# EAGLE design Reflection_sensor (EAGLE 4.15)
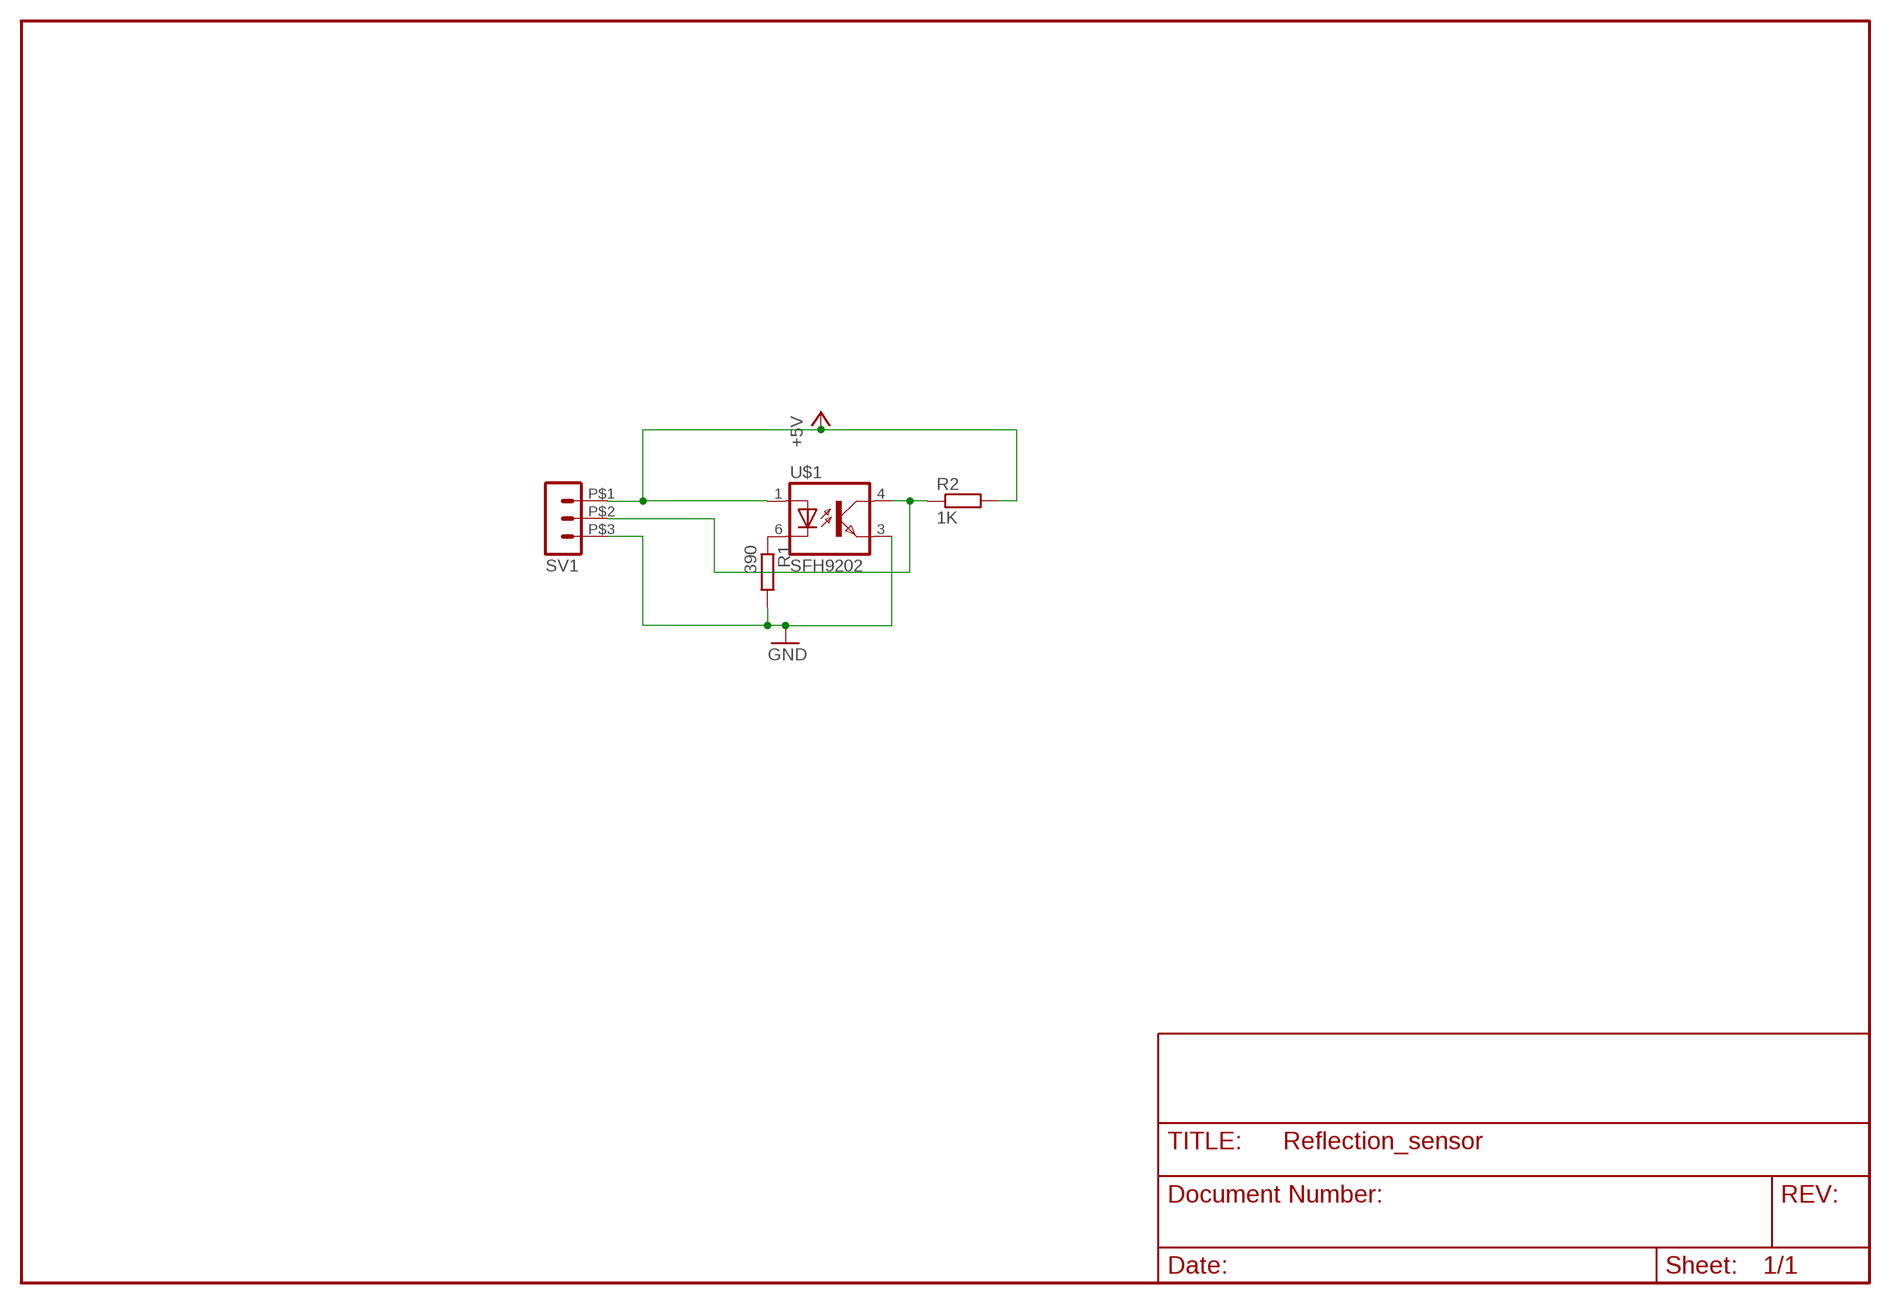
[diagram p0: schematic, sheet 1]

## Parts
R1  390  R-EU_M0805  [M0805]
R2  1K  R-EU_M0805  [M0805]
SV1  MA03-1HOLE  [MA03-1]
U$1  SFH9202  [SFH9202]

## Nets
+5V: R2.2 SV1.P$1 U$1.1(A)
GND: R1.2 SV1.P$3 U$1.3(EMIT)
N$1: R2.1 SV1.P$2 U$1.4(COL)
N$2: R1.1 U$1.6(C)

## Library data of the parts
R1 R2 = rcl:R-EU_: RESISTOR, European symbol
SV1 = Evert:MA03-1: PIN HEADER
U$1 = Evert:SFH9202

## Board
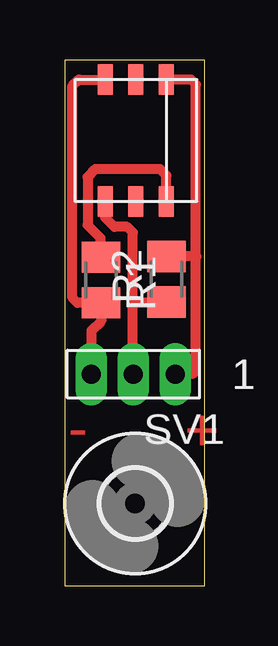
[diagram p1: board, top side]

Size 5.85 x 21.9 mm. Coordinates in mm from the lower left corner, seen from the top.
Outline: 0,0 5.85,0 5.85,21.9 0,21.9 0,0
Copper layers (1*16): Top 0.035mm / dielectric 1.5mm / Bottom 0.035mm
Design rules "default": minimum track width 10mil, minimum drill 24mil, track to track 8mil, track to pad 8mil, pad to pad 8mil, via to via 8mil, smd to smd 8mil, copper to edge 40mil, drill to drill 8mil, minimum pad ring 10mil, minimum via ring 8mil, stop-mask expansion 4mil, vias tented up to drill 0mil, thermal gap 10mil

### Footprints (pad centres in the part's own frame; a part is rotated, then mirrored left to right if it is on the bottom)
M0805 = smd 1.3 x 1.6: 1 -0.95,0; 2 0.95,0
MA03-1 = drill 0.8 long: P$1 -1.75,0; P$2 0,0; P$3 1.75,0
SFH9202 = smd 1.27 x 0.635: 1 -2.54,1.27; 2 -2.54,0; 3 -2.54,-1.27; 4 2.54,-1.27; 5 2.54,0; 6 2.54,1.27
2,8 = hole 2.8: 0,0

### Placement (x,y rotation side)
R1  1.52,12.73 270 top
R2  4.24,12.76 90 top
SV1  2.87,8.8 180 top
U$1  2.97,18.54 270 top
U$2  [2,8]  2.94,3.42 0 top

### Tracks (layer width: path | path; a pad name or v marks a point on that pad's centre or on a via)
+5V
  Top 0.406: U$1.1 5.28,21.08 5.47,20.89 5.47,13.72 | 5.47,13.72 5.47,8.94 5.36,8.83 4.61,8.83 4.62,8.82 SV1.P$1 | 5.47,13.72 5.5,13.72 5.5,13.71 R2.2
GND
  Top 0.406: U$1.3 0.6,21.08 0.33,20.82 0.33,11.99 0.54,11.78 1.47,11.78 1.49,11.76 R1.2 1.52,11.02 1.12,10.62 SV1.P$3
N$1
  Top 0.406: U$1.4 1.7,15.32 2.08,14.95 2.61,14.95 2.84,14.72 2.84,11.81 | SV1.P$2 2.89,8.83 2.84,8.87 2.84,11.81 | SV1.P$2 | 2.84,11.81 2.87,11.81 R2.1
N$2
  Top 0.406: U$1.6 4.24,17.09 3.99,17.35 1.28,17.35 0.96,17.02 0.96,15.02 1.49,14.48 1.49,13.76 1.54,13.72 1.52,13.7 R1.1

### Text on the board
Top: - | +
